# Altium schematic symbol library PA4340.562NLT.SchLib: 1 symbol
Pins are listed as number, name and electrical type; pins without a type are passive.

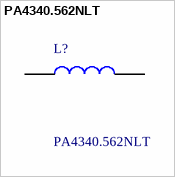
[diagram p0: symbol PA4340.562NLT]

## PA4340.562NLT
designator L?
Fixed Inductors 5.6uH 4.25A 3mm 20% Low Prof; Manufacturer_Name: Yageo Group
footprint PA4340562NLT
pins: 1, 2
